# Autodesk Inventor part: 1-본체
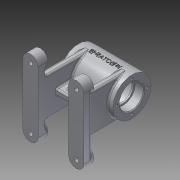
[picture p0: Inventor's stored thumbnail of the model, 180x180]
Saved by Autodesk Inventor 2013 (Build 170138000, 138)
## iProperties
Created: 2015-11
Part Number: 1-본체
Material: 알루미늄 6061
Document SubType Name: Modeling
Designer: Administrator
Density: 2.40759 g/cm^3
Mass: 319 g
Surface Area: 459.581 cm^2
Volume: 132.498 cm^3
Author: Administrator
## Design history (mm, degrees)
sketch "스케치1"
  geometry: L1 (-20, 40)-(-20, -40); L2 (-40, 40)-(-40, -40); L3 (0, 38.699)-(0, -51.087); A1 r 10 centre (-30, 40) between (-20, 40) and (-40, 40); A2 r 10 centre (-30, -40) between (-20, -40) and (-40, -40); 2 further points
  constraints: 6 end point, 4 point on circle, 4 tangent, 2 centre point, 1 horizontal alignment, 1 midpoint, 1 parallel, 1 point on line, 1 vertical, 1 vertical alignment
  dimensions: "d0" = 20 diameter of A1; "d2" = 80 distance of A2.centre A1.centre; "d3" = 80 diameter of L2 L3
extrude "돌출1" new body sketch "스케치1" distance "d4" = 10; taper "d5" = 0 deg
sketch "스케치2"
  geometry: C1 r 10 at (30, -40); C2 r 10 at (30, 40); A1 r 10 centre (30, -40) between (20, -40) and (40, -40) reference; A2 r 10 centre (30, 40) between (40, 40) and (20, 40) reference; 1 further point
  constraints: 2 centre point, 2 concentric
  dimensions: "d6" = 20 diameter of C1; "d8" = 20 diameter of C2
extrude "돌출2" join sketch "스케치2" distance "d9" = 3; taper "d10" = 0 deg
sketch "스케치3"
  geometry: L1 (20, -25)-(28, -25); L2 (28, -25)-(28, 25); L3 (28, 25)-(20, 25); L4 (20, 25)-(20, -25); L5 (20, 40)-(20, -40) reference; 2 further points
  constraints: 8 end point, 2 midpoint, 2 parallel, 1 horizontal, 1 perpendicular
  dimensions: "d11" = 50 distance of L3.end L1.start; "d13" = 8 distance of L1.start L1.end
extrude "돌출3" join sketch "스케치3" distance "d14" = 58; taper "d15" = 0 deg
fillet "모깎기1" dims "d16" = 2
sketch "스케치4"
  geometry: L1 (0, -40)-(0, 40) reference; C1 r 25 at (68, 0); 1 further point
  constraints: 1 centre point, 1 horizontal alignment
  dimensions: "d17" = 50 diameter of C1; "d19" = 68 distance from line of L1 C1.centre
extrude "돌출4" join sketch "스케치4" stored distance "d20" = 70; taper "d21" = 0 deg
sketch "스케치5"
  geometry: L1 (-20, 49.257)-(20, 49.257); L2 (20, 49.257)-(20, 23); L3 (20, 23)-(-20, 23); L4 (-20, 23)-(-20, 49.257); L5 (-35, 43)-(35, 43) reference; L6 (-20, 12)-(-20, 68) reference; L7 (20, 12)-(20, 68) reference; 1 further point
  constraints: 8 end point, 2 parallel, 2 point on line, 1 horizontal, 1 perpendicular
  dimensions: "d22" = 20 distance between parallel lines of L3 L5
extrude "돌출5" join sketch "스케치5" stored distance "d23" = 8; taper "d24" = 0 deg
sketch "스케치6"
  geometry: L1 (-46.712, 68)-(47.627, 68); L2 (-35, 93)-(-35, 43) reference; L3 (-35, 84)-(-23.3, 84); L4 (-23, 83.7)-(-23, 82); L5 (-23, 82)-(-21, 82); L6 (-21, 82)-(-21, 86); L7 (-18, 89)-(18, 89); L8 (21, 86)-(21, 82); L9 (21, 82)-(23, 82); L10 (23, 82)-(23, 83.7); L11 (23.3, 84)-(35, 84); L12 (35, 43)-(35, 93) reference; L13 (20, 43.322)-(-20, 43.322) reference; L14 (-35, 84)-(-35, 68); L15 (35, 84)-(35, 68); L16 (-35, 68)-(35, 68); A1 r 0.3 centre (-23.3, 83.7) between (-23, 83.7) and (-23.3, 84); A2 r 0.3 centre (23.3, 83.7) between (23.3, 84) and (23, 83.7); A3 r 3 centre (-18, 86) between (-18, 89) and (-21, 86); A4 r 3 centre (18, 86) between (21, 86) and (18, 89); 7 further points
  constraints: 26 end point, 11 point on line, 8 point on circle, 8 tangent, 5 parallel, 4 centre point, 4 midpoint, 3 collinear, 2 equal radius, 2 perpendicular, 1 horizontal, 1 vertical alignment
  dimensions: "d25" = 32 diameter of L3 L1; "d27" = 28 diameter of L5 L1; "d28" = 42 diameter of L7 L1; "d29" = 28 diameter of L9 L1; "d30" = 32 diameter of L11 L1; "d31" = 42 distance between parallel lines of L8 L6; "d32" = 12 distance between parallel lines of L2 L4; "d33" = 12 distance between parallel lines of L12 L10; "d35" = 0.3 radius of A1; "d36" = 3 radius of A3
revolve "회전1" sketch "스케치6" stored, may be unused: angle "d34" = 90 deg
chamfer "모따기1" distance "d37" = 1; stored, may be unused: second distance "d38" = 2, angle "d39" = 45 deg
sketch "스케치7"
  geometry: L1 (-8, 36.5)-(8, 36.5); L2 (8, 29.5)-(-8, 29.5); L3 (-20, 23)-(20, 23) reference; L4 (40, 0)-(20, 0) reference; A1 r 3.5 centre (-8, 33) between (-8, 36.5) and (-8, 29.5); A2 r 3.5 centre (8, 33) between (8, 36.5) and (8, 29.5); 5 further points
  constraints: 4 end point, 4 midpoint, 4 point on circle, 4 tangent, 2 centre point, 2 vertical alignment
  dimensions: "d40" = 7 diameter of A1; "d43" = 23 dimension on A2 A1; "d44" = 7 diameter of A2; "d45" = 33 distance from line of L4 A2.centre
extrude "돌출6" cut sketch "스케치7" distance "d46" = 8; taper "d47" = 0 deg
sketch "스케치8"
  geometry: L1 (0, 0)-(60, 0); L2 (60, 0)-(60, 80); L3 (60, 80)-(0, 80); L4 (0, 80)-(0, 0); C1 r 10 at (60, 0) reference; C2 r 10 at (0, 80) reference; 1 further point
  constraints: 8 end point, 2 coincident, 2 parallel, 1 horizontal, 1 perpendicular
  dimensions: "d67" = 60 distance of L1.start L1.end (derived); "d68" = 80 distance of L3.end L1.start (derived)
  node "투영된 루프1"
  node "투영된 루프2"
hole "구멍1" sketch "스케치8" diameter "d48" = 12; stored, may be unused: countersink angle "d52" = 90 deg, drill point angle "d54" = 0 deg; dims "d49" = 6, "d50" = 12, "d51" = 4, "d53" = 4
fillet "모깎기2" dims "d55" = 0.3
hole "구멍2" diameter "d58" = 6; stored, may be unused: countersink angle "d62" = 90 deg, drill point angle "d64" = 0 deg; dims "d59" = 6, "d60" = 8, "d61" = 4, "d63" = 20, "d65" = 10, "d66" = 10
fillet "모깎기3" dims "d75" = 2
sketch "스케치9"
  geometry: L1 (0, 0)-(0, 20); C1 r 25 at (0, 0) reference; C2 r 17 at (0, 0) reference; 1 further point
  constraints: 2 coincident, 2 end point, 1 vertical
  dimensions: "d77" = 20 distance of L1.start L1.end
hole "구멍3" sketch "스케치9" at (0, 20) diameter "d80" = 3.242; stored, may be unused: countersink angle "d84" = 90 deg, drill point angle "d86" = 118 deg; dims "d81" = 8, "d82" = 9, "d83" = 4, "d85" = 10
sketch "스케치10"
  geometry: L1 (0, 0)-(0, 20); C1 r 18 at (0, 0) reference; 1 further point
  constraints: 2 coincident, 2 end point, 1 vertical
  dimensions: "d90" = 20 distance of L1.start L1.end
hole "구멍4" sketch "스케치10" at (0, 20) diameter "d92" = 3.242; stored, may be unused: countersink angle "d96" = 90 deg, drill point angle "d98" = 118 deg; dims "d93" = 8, "d94" = 9, "d95" = 4, "d97" = 10
node "작업 평면3"
  node "작업 평면2"
sketch "스케치12"
  geometry: C1 r 5 at (0, 0); 1 further point
  constraints: 1 centre point, 1 coincident
  dimensions: "d104" = 10 diameter of C1
extrude "돌출7" join sketch "스케치12" distance "d106" = 4; taper "d107" = 0 deg
hole "구멍5" diameter "d110" = 5.188; stored, may be unused: countersink angle "d114" = 90 deg, drill point angle "d116" = 118 deg; dims "d108" = 10, "d109" = 10, "d111" = 15, "d112" = 9, "d113" = 4, "d115" = 20
sketch "스케치13"
  geometry: L1 (68, 0)-(43.751, -14); L2 (68, 0)-(44.303, 0); C1 r 17 at (68, 0) reference; 1 further point
  constraints: 4 end point, 1 horizontal
  dimensions: "d117" = 30 deg angle of L1 L2; "d118" = 28 distance of L1.start L1.end
node "작업 평면4"
sketch "스케치14"
  geometry: C1 r 6 at (0, 0); 1 further point
  constraints: 1 centre point
  dimensions: "d119" = 12 diameter of C1
extrude "돌출8" join sketch "스케치14" stored distance "d121" = 10; taper "d122" = 0 deg
hole "구멍6" diameter "d125" = 5.188; stored, may be unused: countersink angle "d129" = 90 deg, drill point angle "d131" = 118 deg; dims "d123" = 10, "d124" = 10, "d126" = 15, "d127" = 9, "d128" = 4, "d130" = 20
fillet "모깎기4" dims "d132" = 2
node "작업 평면5"
sketch "스케치15"
  geometry: L1 (-14.925, 2.384)-(14.925, 2.384); L2 (14.925, 2.384)-(14.925, -2.384); L3 (14.925, -2.384)-(-14.925, -2.384); L4 (-14.925, -2.384)-(-14.925, 2.384); L5 (-35, 25)-(-35, -25) reference; L6 (-35, 25)-(35, 25) reference; 5 further points
  constraints: 4 midpoint, 1 horizontal alignment, 1 vertical alignment, 2 other
feature "엠보싱1" sketch "스케치15" dims "d0" = 20, "d2" = 80, "d3" = 80, "d133" = 0.5, "d134" = 0
node "솔리드1"
mirror "대칭1"
pattern_linear "직사각형 패턴1"
pattern_circular "원형 패턴1" dims angle "d88" = 360 deg
pattern_circular "원형 패턴2" dims angle "d100" = 360 deg
node "투영된 루프3"
other parameters: "d103" = 3
